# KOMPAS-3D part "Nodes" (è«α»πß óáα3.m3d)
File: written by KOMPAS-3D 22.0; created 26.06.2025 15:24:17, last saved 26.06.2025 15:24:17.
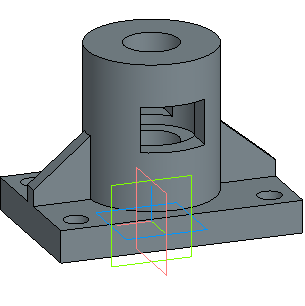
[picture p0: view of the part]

Document properties: Автор: Helen; Полное имя файла: D:\MY\WORK\MPEI\ППЭ_2025-2026\Варианты\Вар 3 СБ\Корпус вар3.m3d

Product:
- Part/product: Nodes

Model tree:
1. Операция без истории:1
